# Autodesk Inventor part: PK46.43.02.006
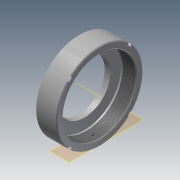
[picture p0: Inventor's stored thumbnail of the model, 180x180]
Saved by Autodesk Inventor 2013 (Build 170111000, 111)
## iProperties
Shininess: 64.0
Length Units: 11269
Angle Units: 11279
Time Units: 11290
Mass Units: 11283
Length Display Precision: 3
Angle Display Precision: 2
Compacted: True
Part Number: PK46.43.02.006
Document SubType Name: Modeling
Created: 2004-11
Material: Steel, High Strength Low Alloy
Designer: ELarisa
Manufacturer: Standard
Standards Organization: Custom
Density: 7.84 g/cm^3
Mass: 6438.98 g
Surface Area: 1201.69 cm^2
Volume: 821.298 cm^3
Density: 0.0
Volumn: 0.0
Area: 0.0
PropertySet Name: Model Information
Control State: 0
Master: False
Checked Out: False
Checked Out Date: 2008-10-09
Last Check In Date: 2008-10-09
Author: ELarisa
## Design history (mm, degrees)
sketch "Эскиз1"
  geometry: L1 (-39.127, -64.027)-(-39.127, 48.473); L2 (-39.127, 48.473)-(15.873, 48.473); L3 (15.873, 48.473)-(15.873, -64.027); L4 (15.873, -64.027)-(-39.127, -64.027); L5 (-39.127, 3.473)-(-24.127, 3.473); L6 (-24.127, 3.473)-(-24.127, 31.473); L7 (-24.127, 31.473)-(-20.127, 31.473); L8 (-20.127, 31.473)-(-19.627, 30.973); L9 (-19.627, 30.973)-(15.873, 30.973)
  constraints: 18 end point, 4 parallel, 3 perpendicular, 2 point on line, 1 vertical
  dimensions: "d0" = 55 distance of L3.end L1.start; "d1" = 112.5 distance of L1.start L1.end; "d2" = 95.5 distance from line of L6.end L4; "d3" = 67.5 distance between parallel lines of L4 L5; "d4" = 95 distance between parallel lines of L4 L9; "d5" = 40 distance between parallel lines of L3 L6; "d6" = 4 distance of L6.end L7.end; "d7" = 135 deg angle of L9 L8
revolve "Вращение1" sketch "Эскиз1" stored, may be unused: angle "d8" = 90 deg
chamfer "Фаска1" distance "d9" = 2; stored, may be unused: second distance "d10" = 2, angle "d50" = 45 deg
feature "Резьба2" dims "d13" = 10, "d14" = 0
chamfer "Фаска2" distance "d15" = 2; stored, may be unused: second distance "d16" = 2, angle "d51" = 45 deg
node "РабОсь1"
node "РабПлоскость1"
sketch "Эскиз2"
  geometry: L1 (-71.163, -64.027)-(153.091, -64.027) reference; L2 (-37.127, 48.473)-(-37.127, -176.527) reference; 2 further points
  dimensions: "d18" = 0 distance from line of L1 point (-2.127, -64.027); "d19" = 35 distance from line of L2 point (-2.127, -64.027)
hole "Отверстие1" sketch "Эскиз2" at (-2.127, -64.027), (121.054, 48.551) diameter "d20" = 6.647; stored, may be unused: countersink angle "d24" = 82 deg, drill point angle "d26" = 118 deg; dims "d21" = 15, "d22" = 11.2, "d23" = 2, "d25" = 20
sketch "Эскиз4"
  geometry: L1 (0, 0)-(-112.708, 0); L2 (0, 0)-(-104.857, -104.857); L3 (-72.478, -79.55)-(-76.014, -76.014); L4 (-76.014, -76.014)-(-79.55, -72.478); L5 (-79.55, -72.478)-(-86.621, -79.55); L6 (-86.621, -79.55)-(-79.55, -86.621); L7 (-79.55, -86.621)-(-72.478, -79.55); C1 r 67.5 at (0, 0) reference; C2 r 110.5 at (0, 0) reference
  constraints: 14 end point, 2 parallel, 2 perpendicular, 1 collinear, 1 horizontal, 1 point on line
  dimensions: "d40" = 45 deg angle of L2 L1; "d41" = 5 distance of L3.start L3.end; "d42" = 5 distance of L3.end L4.end; "d43" = 10 distance of L6.end L3.start; "d44" = 107.5 distance from line of C1.centre L4
extrude "Выдавливание2" cut sketch "Эскиз4" stored distance "d45" = 10; taper "d46" = 0 deg
pattern_circular "Круговой массив2" dims angle "d49" = 360 deg
body "Solid1"
other parameters: "d17" = -112.5
